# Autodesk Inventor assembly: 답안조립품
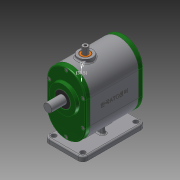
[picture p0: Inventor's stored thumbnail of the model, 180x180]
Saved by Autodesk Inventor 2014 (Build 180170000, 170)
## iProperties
Created: 2016-12
Part Number: 답안조립품
Document SubType Name: Assembly
Designer: user
Mass: 2536.6 g
Surface Area: 2007.09 cm^2
Volume: 723.848 cm^3
Density: 3.50433 g/cm^3
Author: user
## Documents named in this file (14)
- C:\Users\user\Desktop\361208V1006\답안조립품.iam
- C:\Users\user\Desktop\361208V1006\본체.ipt
- C:\Users\user\Desktop\361208V1006\앞커버.ipt
- C:\Users\user\Desktop\361208V1006\뒤커버.ipt
- C:\Users\user\Desktop\361208V1006\베어링 6003.ipt
- C:\Users\user\Desktop\361208V1006\베어링 608.ipt
- C:\Users\user\Desktop\361208V1006\오일실 17 32 8.ipt
- C:\Users\user\Desktop\361208V1006\오일실 8 22 7.ipt
- C:\Users\user\Desktop\361208V1006\서브축.ipt
- C:\Users\user\Desktop\361208V1006\메인축.ipt
- C:\Users\user\Desktop\361208V1006\부시.ipt
- C:\Users\user\Desktop\361208V1006\슬라이더.ipt
- C:\Users\user\Desktop\361208V1006\가변스프링.ipt
- C:\Users\user\Desktop\361208V1006\볼트 M4.ipt
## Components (1 placed, 1 different names)
1. 가변스프링:1 — Mate:2, Mate:3, Mate:4
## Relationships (3: Mate 3)
- Mate:2: 가변스프링:1
- Mate:3: 가변스프링:1
- Mate:4: 가변스프링:1
